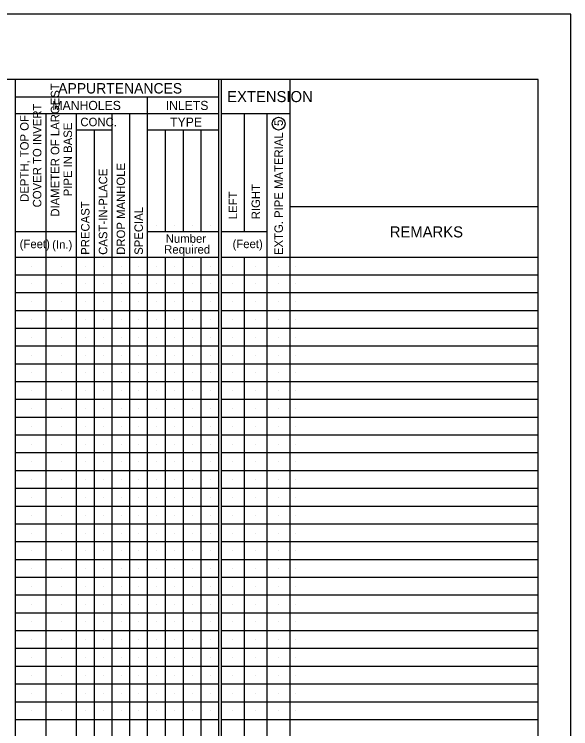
# Model space of a CAD drawing. Extents: x 0 to 1.42, y 0 to 0.92.
# Drawn here: x 1.0608 to 1.4167, y 0.4596 to 0.9167 of the extents above; entities that cross this region are included whole.
import ezdxf

# ---------------------------------------------------------------- set-up
doc = ezdxf.new("R2010")
doc.units = 0
for name, color, linetype in [('#plot_shape', 7, 'Continuous'), ('P_ODOT_PLAN_Border', 7, 'Continuous'), ('P_ODOT_PLAN_General', 7, 'Continuous'), ('P_RDWY_PLAN_NotesTx', 7, 'Continuous')]:
    doc.layers.add(name, color=color, linetype=linetype)

msp = doc.modelspace()

# ---------------------------------------------------------------- linework, layer by layer
at = {"layer": '#plot_shape'}
msp.add_lwpolyline([(0, 0), (1.41667, 0), (1.41667, 0.91667), (0, 0.91667)], close=True, dxfattribs=at)
at = {"layer": 'P_ODOT_PLAN_Border'}
msp.add_lwpolyline([(0.0625, 0.04167), (1.39583, 0.04167), (1.39583, 0.875), (0.0625, 0.875)], close=True, dxfattribs=at)
at = {"layer": 'P_ODOT_PLAN_General'}
for p, q in [((1.06165, 0.26037), (1.06165, 0.875)), ((1.1917, 0.26037), (1.1917, 0.875)), ((1.19333, 0.26037), (1.19333, 0.875)), ((1.23723, 0.26037), (1.23723, 0.875)), ((1.1917, 0.86362), (1.06165, 0.86362)), ((1.14594, 0.26037), (1.14594, 0.86362)), ((1.1917, 0.85305), (1.06165, 0.85305)), ((1.08115, 0.26037), (1.08115, 0.85305)), ((1.10065, 0.26037), (1.10065, 0.85305)), ((1.12341, 0.26037), (1.12341, 0.85305)), ((1.13479, 0.26037), (1.13479, 0.85305)), ((1.23723, 0.85305), (1.19333, 0.85305)), ((1.20796, 0.77744), (1.20796, 0.85305)), ((1.2226, 0.26037), (1.2226, 0.85305)), ((1.12341, 0.84248), (1.10065, 0.84248)), ((1.11203, 0.26037), (1.11203, 0.84248)), ((1.1917, 0.84248), (1.14594, 0.84248)), ((1.15756, 0.77744), (1.15756, 0.84248)), ((1.16894, 0.77744), (1.16894, 0.84248)), ((1.18032, 0.77744), (1.18032, 0.84248)), ((1.23723, 0.7937), (1.39583, 0.7937)), ((1.10065, 0.77744), (1.06165, 0.77744)), ((1.1917, 0.77744), (1.14594, 0.77744)), ((1.2226, 0.77744), (1.19333, 0.77744)), ((1.06165, 0.76118), (1.1917, 0.76118)), ((1.15756, 0.26037), (1.15756, 0.76118)), ((1.16894, 0.26037), (1.16894, 0.76118)), ((1.18032, 0.26037), (1.18032, 0.76118)), ((1.19333, 0.76118), (1.39583, 0.76118)), ((1.20796, 0.26037), (1.20796, 0.76118)), ((1.07152, 0.75549), (1.07152, 0.75549)), ((1.09102, 0.75549), (1.09102, 0.75549)), ((1.10634, 0.75549), (1.10634, 0.75549)), ((1.11772, 0.75549), (1.11772, 0.75549)), ((1.1291, 0.75549), (1.1291, 0.75549)), ((1.14049, 0.75549), (1.14049, 0.75549)), ((1.15187, 0.75549), (1.15187, 0.75549)), ((1.16325, 0.75549), (1.16325, 0.75549)), ((1.17463, 0.75549), (1.17463, 0.75549)), ((1.18601, 0.75549), (1.18601, 0.75549)), ((1.20065, 0.75549), (1.20065, 0.75549)), ((1.21528, 0.75549), (1.21528, 0.75549)), ((1.22992, 0.75549), (1.22992, 0.75549)), ((1.24095, 0.75549), (1.24095, 0.75549)), ((1.1917, 0.7498), (1.06165, 0.7498)), ((1.39583, 0.7498), (1.19333, 0.7498)), ((1.07152, 0.74411), (1.07152, 0.74411)), ((1.09102, 0.74411), (1.09102, 0.74411)), ((1.10634, 0.74411), (1.10634, 0.74411)), ((1.11772, 0.74411), (1.11772, 0.74411)), ((1.1291, 0.74411), (1.1291, 0.74411)), ((1.14049, 0.74411), (1.14049, 0.74411)), ((1.15187, 0.74411), (1.15187, 0.74411)), ((1.16325, 0.74411), (1.16325, 0.74411)), ((1.17463, 0.74411), (1.17463, 0.74411)), ((1.18601, 0.74411), (1.18601, 0.74411)), ((1.20065, 0.74411), (1.20065, 0.74411)), ((1.21528, 0.74411), (1.21528, 0.74411)), ((1.22992, 0.74411), (1.22992, 0.74411)), ((1.24095, 0.74411), (1.24095, 0.74411)), ((1.1917, 0.73842), (1.06165, 0.73842)), ((1.39583, 0.73842), (1.19333, 0.73842)), ((1.07152, 0.73273), (1.07152, 0.73273)), ((1.09102, 0.73273), (1.09102, 0.73273)), ((1.10634, 0.73273), (1.10634, 0.73273)), ((1.11772, 0.73273), (1.11772, 0.73273)), ((1.1291, 0.73273), (1.1291, 0.73273)), ((1.14049, 0.73273), (1.14049, 0.73273)), ((1.15187, 0.73273), (1.15187, 0.73273)), ((1.16325, 0.73273), (1.16325, 0.73273)), ((1.17463, 0.73273), (1.17463, 0.73273)), ((1.18601, 0.73273), (1.18601, 0.73273)), ((1.20065, 0.73273), (1.20065, 0.73273)), ((1.21528, 0.73273), (1.21528, 0.73273)), ((1.22992, 0.73273), (1.22992, 0.73273)), ((1.24095, 0.73273), (1.24095, 0.73273)), ((1.1917, 0.72703), (1.06165, 0.72703)), ((1.39583, 0.72703), (1.19333, 0.72703)), ((1.07152, 0.72134), (1.07152, 0.72134)), ((1.09102, 0.72134), (1.09102, 0.72134)), ((1.10634, 0.72134), (1.10634, 0.72134)), ((1.11772, 0.72134), (1.11772, 0.72134)), ((1.1291, 0.72134), (1.1291, 0.72134)), ((1.14049, 0.72134), (1.14049, 0.72134)), ((1.15187, 0.72134), (1.15187, 0.72134)), ((1.16325, 0.72134), (1.16325, 0.72134)), ((1.17463, 0.72134), (1.17463, 0.72134)), ((1.18601, 0.72134), (1.18601, 0.72134)), ((1.20065, 0.72134), (1.20065, 0.72134)), ((1.21528, 0.72134), (1.21528, 0.72134)), ((1.22992, 0.72134), (1.22992, 0.72134)), ((1.24095, 0.72134), (1.24095, 0.72134)), ((1.1917, 0.71565), (1.06165, 0.71565)), ((1.39583, 0.71565), (1.19333, 0.71565)), ((1.07152, 0.70996), (1.07152, 0.70996)), ((1.09102, 0.70996), (1.09102, 0.70996)), ((1.10634, 0.70996), (1.10634, 0.70996)), ((1.11772, 0.70996), (1.11772, 0.70996)), ((1.1291, 0.70996), (1.1291, 0.70996)), ((1.14049, 0.70996), (1.14049, 0.70996)), ((1.15187, 0.70996), (1.15187, 0.70996)), ((1.16325, 0.70996), (1.16325, 0.70996)), ((1.17463, 0.70996), (1.17463, 0.70996)), ((1.18601, 0.70996), (1.18601, 0.70996)), ((1.20065, 0.70996), (1.20065, 0.70996)), ((1.21528, 0.70996), (1.21528, 0.70996)), ((1.22992, 0.70996), (1.22992, 0.70996)), ((1.24095, 0.70996), (1.24095, 0.70996)), ((1.1917, 0.70427), (1.06165, 0.70427)), ((1.39583, 0.70427), (1.19333, 0.70427)), ((1.07152, 0.69858), (1.07152, 0.69858)), ((1.09102, 0.69858), (1.09102, 0.69858)), ((1.10634, 0.69858), (1.10634, 0.69858)), ((1.11772, 0.69858), (1.11772, 0.69858)), ((1.1291, 0.69858), (1.1291, 0.69858)), ((1.14049, 0.69858), (1.14049, 0.69858)), ((1.15187, 0.69858), (1.15187, 0.69858)), ((1.16325, 0.69858), (1.16325, 0.69858)), ((1.17463, 0.69858), (1.17463, 0.69858)), ((1.18601, 0.69858), (1.18601, 0.69858)), ((1.20065, 0.69858), (1.20065, 0.69858)), ((1.21528, 0.69858), (1.21528, 0.69858)), ((1.22992, 0.69858), (1.22992, 0.69858)), ((1.24095, 0.69858), (1.24095, 0.69858)), ((1.1917, 0.69289), (1.06165, 0.69289)), ((1.39583, 0.69289), (1.19333, 0.69289)), ((1.07152, 0.6872), (1.07152, 0.6872)), ((1.09102, 0.6872), (1.09102, 0.6872)), ((1.10634, 0.6872), (1.10634, 0.6872)), ((1.11772, 0.6872), (1.11772, 0.6872)), ((1.1291, 0.6872), (1.1291, 0.6872)), ((1.14049, 0.6872), (1.14049, 0.6872)), ((1.15187, 0.6872), (1.15187, 0.6872)), ((1.16325, 0.6872), (1.16325, 0.6872)), ((1.17463, 0.6872), (1.17463, 0.6872)), ((1.18601, 0.6872), (1.18601, 0.6872)), ((1.20065, 0.6872), (1.20065, 0.6872)), ((1.21528, 0.6872), (1.21528, 0.6872)), ((1.22992, 0.6872), (1.22992, 0.6872)), ((1.24095, 0.6872), (1.24095, 0.6872)), ((1.1917, 0.68151), (1.06165, 0.68151)), ((1.39583, 0.68151), (1.19333, 0.68151)), ((1.07152, 0.67582), (1.07152, 0.67582)), ((1.09102, 0.67582), (1.09102, 0.67582)), ((1.10634, 0.67582), (1.10634, 0.67582)), ((1.11772, 0.67582), (1.11772, 0.67582)), ((1.1291, 0.67582), (1.1291, 0.67582)), ((1.14049, 0.67582), (1.14049, 0.67582)), ((1.15187, 0.67582), (1.15187, 0.67582)), ((1.16325, 0.67582), (1.16325, 0.67582)), ((1.17463, 0.67582), (1.17463, 0.67582)), ((1.18601, 0.67582), (1.18601, 0.67582)), ((1.20065, 0.67582), (1.20065, 0.67582)), ((1.21528, 0.67582), (1.21528, 0.67582)), ((1.22992, 0.67582), (1.22992, 0.67582)), ((1.24095, 0.67582), (1.24095, 0.67582)), ((1.1917, 0.67012), (1.06165, 0.67012)), ((1.39583, 0.67012), (1.19333, 0.67012)), ((1.07152, 0.66443), (1.07152, 0.66443)), ((1.09102, 0.66443), (1.09102, 0.66443)), ((1.10634, 0.66443), (1.10634, 0.66443)), ((1.11772, 0.66443), (1.11772, 0.66443)), ((1.1291, 0.66443), (1.1291, 0.66443)), ((1.14049, 0.66443), (1.14049, 0.66443)), ((1.15187, 0.66443), (1.15187, 0.66443)), ((1.16325, 0.66443), (1.16325, 0.66443)), ((1.17463, 0.66443), (1.17463, 0.66443)), ((1.18601, 0.66443), (1.18601, 0.66443)), ((1.20065, 0.66443), (1.20065, 0.66443)), ((1.21528, 0.66443), (1.21528, 0.66443)), ((1.22992, 0.66443), (1.22992, 0.66443)), ((1.24095, 0.66443), (1.24095, 0.66443)), ((1.1917, 0.65874), (1.06165, 0.65874)), ((1.39583, 0.65874), (1.19333, 0.65874)), ((1.07152, 0.65305), (1.07152, 0.65305)), ((1.09102, 0.65305), (1.09102, 0.65305)), ((1.10634, 0.65305), (1.10634, 0.65305)), ((1.11772, 0.65305), (1.11772, 0.65305)), ((1.1291, 0.65305), (1.1291, 0.65305)), ((1.14049, 0.65305), (1.14049, 0.65305)), ((1.15187, 0.65305), (1.15187, 0.65305)), ((1.16325, 0.65305), (1.16325, 0.65305)), ((1.17463, 0.65305), (1.17463, 0.65305)), ((1.18601, 0.65305), (1.18601, 0.65305)), ((1.20065, 0.65305), (1.20065, 0.65305)), ((1.21528, 0.65305), (1.21528, 0.65305)), ((1.22992, 0.65305), (1.22992, 0.65305)), ((1.24095, 0.65305), (1.24095, 0.65305)), ((1.1917, 0.64736), (1.06165, 0.64736)), ((1.39583, 0.64736), (1.19333, 0.64736)), ((1.07152, 0.64167), (1.07152, 0.64167)), ((1.09102, 0.64167), (1.09102, 0.64167)), ((1.10634, 0.64167), (1.10634, 0.64167)), ((1.11772, 0.64167), (1.11772, 0.64167)), ((1.1291, 0.64167), (1.1291, 0.64167)), ((1.14049, 0.64167), (1.14049, 0.64167)), ((1.15187, 0.64167), (1.15187, 0.64167)), ((1.16325, 0.64167), (1.16325, 0.64167)), ((1.17463, 0.64167), (1.17463, 0.64167)), ((1.18601, 0.64167), (1.18601, 0.64167)), ((1.20065, 0.64167), (1.20065, 0.64167)), ((1.21528, 0.64167), (1.21528, 0.64167)), ((1.22992, 0.64167), (1.22992, 0.64167)), ((1.24095, 0.64167), (1.24095, 0.64167)), ((1.1917, 0.63598), (1.06165, 0.63598)), ((1.39583, 0.63598), (1.19333, 0.63598)), ((1.07152, 0.63029), (1.07152, 0.63029)), ((1.09102, 0.63029), (1.09102, 0.63029)), ((1.10634, 0.63029), (1.10634, 0.63029)), ((1.11772, 0.63029), (1.11772, 0.63029)), ((1.1291, 0.63029), (1.1291, 0.63029)), ((1.14049, 0.63029), (1.14049, 0.63029)), ((1.15187, 0.63029), (1.15187, 0.63029)), ((1.16325, 0.63029), (1.16325, 0.63029)), ((1.17463, 0.63029), (1.17463, 0.63029)), ((1.18601, 0.63029), (1.18601, 0.63029)), ((1.20065, 0.63029), (1.20065, 0.63029)), ((1.21528, 0.63029), (1.21528, 0.63029)), ((1.22992, 0.63029), (1.22992, 0.63029)), ((1.24095, 0.63029), (1.24095, 0.63029)), ((1.1917, 0.6246), (1.06165, 0.6246)), ((1.39583, 0.6246), (1.19333, 0.6246)), ((1.07152, 0.61891), (1.07152, 0.61891)), ((1.09102, 0.61891), (1.09102, 0.61891)), ((1.10634, 0.61891), (1.10634, 0.61891)), ((1.11772, 0.61891), (1.11772, 0.61891)), ((1.1291, 0.61891), (1.1291, 0.61891)), ((1.14049, 0.61891), (1.14049, 0.61891)), ((1.15187, 0.61891), (1.15187, 0.61891)), ((1.16325, 0.61891), (1.16325, 0.61891)), ((1.17463, 0.61891), (1.17463, 0.61891)), ((1.18601, 0.61891), (1.18601, 0.61891)), ((1.20065, 0.61891), (1.20065, 0.61891)), ((1.21528, 0.61891), (1.21528, 0.61891)), ((1.22992, 0.61891), (1.22992, 0.61891)), ((1.24095, 0.61891), (1.24095, 0.61891)), ((1.1917, 0.61321), (1.06165, 0.61321)), ((1.39583, 0.61321), (1.19333, 0.61321)), ((1.07152, 0.60752), (1.07152, 0.60752)), ((1.09102, 0.60752), (1.09102, 0.60752)), ((1.10634, 0.60752), (1.10634, 0.60752)), ((1.11772, 0.60752), (1.11772, 0.60752)), ((1.1291, 0.60752), (1.1291, 0.60752)), ((1.14049, 0.60752), (1.14049, 0.60752)), ((1.15187, 0.60752), (1.15187, 0.60752)), ((1.16325, 0.60752), (1.16325, 0.60752)), ((1.17463, 0.60752), (1.17463, 0.60752)), ((1.18601, 0.60752), (1.18601, 0.60752)), ((1.20065, 0.60752), (1.20065, 0.60752)), ((1.21528, 0.60752), (1.21528, 0.60752)), ((1.22992, 0.60752), (1.22992, 0.60752)), ((1.24095, 0.60752), (1.24095, 0.60752)), ((1.1917, 0.60183), (1.06165, 0.60183)), ((1.39583, 0.60183), (1.19333, 0.60183)), ((1.07152, 0.59614), (1.07152, 0.59614)), ((1.09102, 0.59614), (1.09102, 0.59614)), ((1.10634, 0.59614), (1.10634, 0.59614)), ((1.11772, 0.59614), (1.11772, 0.59614)), ((1.1291, 0.59614), (1.1291, 0.59614)), ((1.14049, 0.59614), (1.14049, 0.59614)), ((1.15187, 0.59614), (1.15187, 0.59614)), ((1.16325, 0.59614), (1.16325, 0.59614)), ((1.17463, 0.59614), (1.17463, 0.59614)), ((1.18601, 0.59614), (1.18601, 0.59614)), ((1.20065, 0.59614), (1.20065, 0.59614)), ((1.21528, 0.59614), (1.21528, 0.59614)), ((1.22992, 0.59614), (1.22992, 0.59614)), ((1.24095, 0.59614), (1.24095, 0.59614)), ((1.1917, 0.59045), (1.06165, 0.59045)), ((1.39583, 0.59045), (1.19333, 0.59045)), ((1.07152, 0.58476), (1.07152, 0.58476)), ((1.09102, 0.58476), (1.09102, 0.58476)), ((1.10634, 0.58476), (1.10634, 0.58476)), ((1.11772, 0.58476), (1.11772, 0.58476)), ((1.1291, 0.58476), (1.1291, 0.58476)), ((1.14049, 0.58476), (1.14049, 0.58476)), ((1.15187, 0.58476), (1.15187, 0.58476)), ((1.16325, 0.58476), (1.16325, 0.58476)), ((1.17463, 0.58476), (1.17463, 0.58476)), ((1.18601, 0.58476), (1.18601, 0.58476)), ((1.20065, 0.58476), (1.20065, 0.58476)), ((1.21528, 0.58476), (1.21528, 0.58476)), ((1.22992, 0.58476), (1.22992, 0.58476)), ((1.24095, 0.58476), (1.24095, 0.58476)), ((1.1917, 0.57907), (1.06165, 0.57907)), ((1.39583, 0.57907), (1.19333, 0.57907)), ((1.07152, 0.57338), (1.07152, 0.57338)), ((1.09102, 0.57338), (1.09102, 0.57338)), ((1.10634, 0.57338), (1.10634, 0.57338)), ((1.11772, 0.57338), (1.11772, 0.57338)), ((1.1291, 0.57338), (1.1291, 0.57338)), ((1.14049, 0.57338), (1.14049, 0.57338)), ((1.15187, 0.57338), (1.15187, 0.57338)), ((1.16325, 0.57338), (1.16325, 0.57338)), ((1.17463, 0.57338), (1.17463, 0.57338)), ((1.18601, 0.57338), (1.18601, 0.57338)), ((1.20065, 0.57338), (1.20065, 0.57338)), ((1.21528, 0.57338), (1.21528, 0.57338)), ((1.22992, 0.57338), (1.22992, 0.57338)), ((1.24095, 0.57338), (1.24095, 0.57338)), ((1.1917, 0.56769), (1.06165, 0.56769)), ((1.39583, 0.56769), (1.19333, 0.56769)), ((1.07152, 0.562), (1.07152, 0.562)), ((1.09102, 0.562), (1.09102, 0.562)), ((1.10634, 0.562), (1.10634, 0.562)), ((1.11772, 0.562), (1.11772, 0.562)), ((1.1291, 0.562), (1.1291, 0.562)), ((1.14049, 0.562), (1.14049, 0.562)), ((1.15187, 0.562), (1.15187, 0.562)), ((1.16325, 0.562), (1.16325, 0.562)), ((1.17463, 0.562), (1.17463, 0.562)), ((1.18601, 0.562), (1.18601, 0.562)), ((1.20065, 0.562), (1.20065, 0.562)), ((1.21528, 0.562), (1.21528, 0.562)), ((1.22992, 0.562), (1.22992, 0.562)), ((1.24095, 0.562), (1.24095, 0.562)), ((1.1917, 0.5563), (1.06165, 0.5563)), ((1.39583, 0.5563), (1.19333, 0.5563)), ((1.07152, 0.55061), (1.07152, 0.55061)), ((1.09102, 0.55061), (1.09102, 0.55061)), ((1.10634, 0.55061), (1.10634, 0.55061)), ((1.11772, 0.55061), (1.11772, 0.55061)), ((1.1291, 0.55061), (1.1291, 0.55061)), ((1.14049, 0.55061), (1.14049, 0.55061)), ((1.15187, 0.55061), (1.15187, 0.55061)), ((1.16325, 0.55061), (1.16325, 0.55061)), ((1.17463, 0.55061), (1.17463, 0.55061)), ((1.18601, 0.55061), (1.18601, 0.55061)), ((1.20065, 0.55061), (1.20065, 0.55061)), ((1.21528, 0.55061), (1.21528, 0.55061)), ((1.22992, 0.55061), (1.22992, 0.55061)), ((1.24095, 0.55061), (1.24095, 0.55061)), ((1.1917, 0.54492), (1.06165, 0.54492)), ((1.39583, 0.54492), (1.19333, 0.54492)), ((1.07152, 0.53923), (1.07152, 0.53923)), ((1.09102, 0.53923), (1.09102, 0.53923)), ((1.10634, 0.53923), (1.10634, 0.53923)), ((1.11772, 0.53923), (1.11772, 0.53923)), ((1.1291, 0.53923), (1.1291, 0.53923)), ((1.14049, 0.53923), (1.14049, 0.53923)), ((1.15187, 0.53923), (1.15187, 0.53923)), ((1.16325, 0.53923), (1.16325, 0.53923)), ((1.17463, 0.53923), (1.17463, 0.53923)), ((1.18601, 0.53923), (1.18601, 0.53923)), ((1.20065, 0.53923), (1.20065, 0.53923)), ((1.21528, 0.53923), (1.21528, 0.53923)), ((1.22992, 0.53923), (1.22992, 0.53923)), ((1.24095, 0.53923), (1.24095, 0.53923)), ((1.1917, 0.53354), (1.06165, 0.53354)), ((1.39583, 0.53354), (1.19333, 0.53354)), ((1.07152, 0.52785), (1.07152, 0.52785)), ((1.09102, 0.52785), (1.09102, 0.52785)), ((1.10634, 0.52785), (1.10634, 0.52785)), ((1.11772, 0.52785), (1.11772, 0.52785)), ((1.1291, 0.52785), (1.1291, 0.52785)), ((1.14049, 0.52785), (1.14049, 0.52785)), ((1.15187, 0.52785), (1.15187, 0.52785)), ((1.16325, 0.52785), (1.16325, 0.52785)), ((1.17463, 0.52785), (1.17463, 0.52785)), ((1.18601, 0.52785), (1.18601, 0.52785)), ((1.20065, 0.52785), (1.20065, 0.52785)), ((1.21528, 0.52785), (1.21528, 0.52785)), ((1.22992, 0.52785), (1.22992, 0.52785)), ((1.24095, 0.52785), (1.24095, 0.52785)), ((1.1917, 0.52216), (1.06165, 0.52216)), ((1.39583, 0.52216), (1.19333, 0.52216)), ((1.07152, 0.51647), (1.07152, 0.51647)), ((1.09102, 0.51647), (1.09102, 0.51647)), ((1.10634, 0.51647), (1.10634, 0.51647)), ((1.11772, 0.51647), (1.11772, 0.51647)), ((1.1291, 0.51647), (1.1291, 0.51647)), ((1.14049, 0.51647), (1.14049, 0.51647)), ((1.15187, 0.51647), (1.15187, 0.51647)), ((1.16325, 0.51647), (1.16325, 0.51647)), ((1.17463, 0.51647), (1.17463, 0.51647)), ((1.18601, 0.51647), (1.18601, 0.51647)), ((1.20065, 0.51647), (1.20065, 0.51647)), ((1.21528, 0.51647), (1.21528, 0.51647)), ((1.22992, 0.51647), (1.22992, 0.51647)), ((1.24095, 0.51647), (1.24095, 0.51647)), ((1.1917, 0.51078), (1.06165, 0.51078)), ((1.39583, 0.51078), (1.19333, 0.51078)), ((1.07152, 0.50509), (1.07152, 0.50509)), ((1.09102, 0.50509), (1.09102, 0.50509)), ((1.10634, 0.50509), (1.10634, 0.50509)), ((1.11772, 0.50509), (1.11772, 0.50509)), ((1.1291, 0.50509), (1.1291, 0.50509)), ((1.14049, 0.50509), (1.14049, 0.50509)), ((1.15187, 0.50509), (1.15187, 0.50509)), ((1.16325, 0.50509), (1.16325, 0.50509)), ((1.17463, 0.50509), (1.17463, 0.50509)), ((1.18601, 0.50509), (1.18601, 0.50509)), ((1.20065, 0.50509), (1.20065, 0.50509)), ((1.21528, 0.50509), (1.21528, 0.50509)), ((1.22992, 0.50509), (1.22992, 0.50509)), ((1.24095, 0.50509), (1.24095, 0.50509)), ((1.1917, 0.49939), (1.06165, 0.49939)), ((1.39583, 0.49939), (1.19333, 0.49939)), ((1.07152, 0.4937), (1.07152, 0.4937)), ((1.09102, 0.4937), (1.09102, 0.4937)), ((1.10634, 0.4937), (1.10634, 0.4937)), ((1.11772, 0.4937), (1.11772, 0.4937)), ((1.1291, 0.4937), (1.1291, 0.4937)), ((1.14049, 0.4937), (1.14049, 0.4937)), ((1.15187, 0.4937), (1.15187, 0.4937)), ((1.16325, 0.4937), (1.16325, 0.4937)), ((1.17463, 0.4937), (1.17463, 0.4937)), ((1.18601, 0.4937), (1.18601, 0.4937)), ((1.20065, 0.4937), (1.20065, 0.4937)), ((1.21528, 0.4937), (1.21528, 0.4937)), ((1.22992, 0.4937), (1.22992, 0.4937)), ((1.24095, 0.4937), (1.24095, 0.4937)), ((1.1917, 0.48801), (1.06165, 0.48801)), ((1.39583, 0.48801), (1.19333, 0.48801)), ((1.07152, 0.48232), (1.07152, 0.48232)), ((1.09102, 0.48232), (1.09102, 0.48232)), ((1.10634, 0.48232), (1.10634, 0.48232)), ((1.11772, 0.48232), (1.11772, 0.48232)), ((1.1291, 0.48232), (1.1291, 0.48232)), ((1.14049, 0.48232), (1.14049, 0.48232)), ((1.15187, 0.48232), (1.15187, 0.48232)), ((1.16325, 0.48232), (1.16325, 0.48232)), ((1.17463, 0.48232), (1.17463, 0.48232)), ((1.18601, 0.48232), (1.18601, 0.48232)), ((1.20065, 0.48232), (1.20065, 0.48232)), ((1.21528, 0.48232), (1.21528, 0.48232)), ((1.22992, 0.48232), (1.22992, 0.48232)), ((1.24095, 0.48232), (1.24095, 0.48232)), ((1.1917, 0.47663), (1.06165, 0.47663)), ((1.39583, 0.47663), (1.19333, 0.47663)), ((1.07152, 0.47094), (1.07152, 0.47094)), ((1.09102, 0.47094), (1.09102, 0.47094)), ((1.10634, 0.47094), (1.10634, 0.47094)), ((1.11772, 0.47094), (1.11772, 0.47094)), ((1.1291, 0.47094), (1.1291, 0.47094)), ((1.14049, 0.47094), (1.14049, 0.47094)), ((1.15187, 0.47094), (1.15187, 0.47094)), ((1.16325, 0.47094), (1.16325, 0.47094)), ((1.17463, 0.47094), (1.17463, 0.47094)), ((1.18601, 0.47094), (1.18601, 0.47094)), ((1.20065, 0.47094), (1.20065, 0.47094)), ((1.21528, 0.47094), (1.21528, 0.47094)), ((1.22992, 0.47094), (1.22992, 0.47094)), ((1.24095, 0.47094), (1.24095, 0.47094)), ((1.1917, 0.46525), (1.06165, 0.46525)), ((1.39583, 0.46525), (1.19333, 0.46525))]:
    msp.add_line(p, q, dxfattribs=at)
at = {"layer": 'P_RDWY_PLAN_NotesTx'}
for p, q in [((1.15187, 0.78161), (1.15187, 0.78161)), ((1.16325, 0.78161), (1.16325, 0.78161)), ((1.17463, 0.78161), (1.17463, 0.78161)), ((1.18601, 0.78161), (1.18601, 0.78161)), ((1.10622, 0.76278), (1.10622, 0.76278)), ((1.1176, 0.76278), (1.1176, 0.76278)), ((1.12899, 0.76278), (1.12899, 0.76278)), ((1.14037, 0.76278), (1.14037, 0.76278))]:
    msp.add_line(p, q, dxfattribs=at)
msp.add_circle((1.2299, 0.84667), 0.00407, dxfattribs=at)

# ---------------------------------------------------------------- texts
for s, height, p in [('DIAMETER OF LARGEST', 0.0054167, (1.08961, 0.7872)), ('COVER TO INVERT', 0.0054167, (1.07815, 0.79312)), ('DEPTH, TOP OF', 0.0054167, (1.07002, 0.79664)), ('PIPE IN BASE', 0.0054167, (1.09774, 0.80022)), ('5', 0.00542, (1.23261, 0.84521)), ('EXTG. PIPE MATERIAL', 0.0054167, (1.23262, 0.76263)), ('DROP MANHOLE', 0.0054167, (1.13169, 0.76278)), ('CAST-IN-PLACE', 0.0054167, (1.12031, 0.76278)), ('RIGHT', 0.005417, (1.21799, 0.78553)), ('LEFT', 0.005417, (1.20336, 0.78553)), ('PRECAST', 0.005417, (1.10893, 0.76278)), ('SPECIAL', 0.005417, (1.14308, 0.76278))]:
    msp.add_text(s, height=height, rotation=90, dxfattribs=at).set_placement(p)
for s, height, p in [('APPURTENANCES', 0.0066667, (1.08891, 0.86598)), ('EXTENSION', 0.007083, (1.19697, 0.86048)), ('MANHOLES', 0.005833, (1.08522, 0.85542)), ('INLETS', 0.005833, (1.15767, 0.85542)), ('CONC.', 0.005417, (1.1031, 0.84506)), ('TYPE', 0.005833, (1.16049, 0.84478)), ('REMARKS', 0.007083, (1.30096, 0.7739)), ('(Feet)', 0.005417, (1.06428, 0.767)), ('Number', 0.005417, (1.15772, 0.77046)), ('(Feet)', 0.005417, (1.20042, 0.76705)), ('(In.)', 0.005417, (1.08505, 0.76663)), ('Required', 0.005417, (1.15668, 0.7635))]:
    msp.add_text(s, height=height, dxfattribs=at).set_placement(p)

doc.saveas('drawing.dxf')
